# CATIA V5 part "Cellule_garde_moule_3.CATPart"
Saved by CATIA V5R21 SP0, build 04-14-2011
Part number: Moule_cellule_garde.1
Bounding box of the stored display mesh (mm): x -18 to 18, y -75 to 75, z -17 to 0
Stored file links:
  C:\Users\zerma\Pictures\Moule_3\Cellule_garde_moule_3.CATPart
  Product1.CATProduct
  C:\Users\zerma\Pictures\Moule\Moule_v1.CATPart
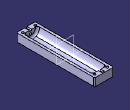
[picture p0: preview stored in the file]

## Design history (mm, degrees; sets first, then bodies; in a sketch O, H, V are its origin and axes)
Body1 (main body)
  Sketch1 on yz-plane, origin (0, 0, 0), H (0, 1, 0), V (0, 0, 1)
    line L1 (-95, -12.5) -> (95, -12.5)
    point P1 (-95, -12.5)
    line L2 (-100, -15) -> (100, -15)
    point P3 (-100, -15)
    line L3 (-95, -12.5) -> (-95, 0)
    point P5 (-95, 0)
    line L4 (-100, -15) -> (-100, 0)
    point P6 (-100, 0)
    line L5 (-95, 0) -> (-100, 0)
    point P7 (100, 0)
    point P8 (100, -15)
    line L6 (100, -15) -> (100, 0)
    point P9 (95, 0)
    line L7 (95, 0) -> (100, 0)
    point P10 (95, -12.5)
    line L8 (95, -12.5) -> (95, 0)
    distance L1 H = 12.5
    distance L1 L2 = 2.5
    length L4 = 15
    distance L4 L3 = 5
    length L1 = 190
    length L2 = 200
    distance V L3 = 95
    horizontal: L1 H, L2 H, L5 H
    vertical: L3 V, L4 V
    symmetry: P6 P7 V, P3 P8 V, L4 L6 V, P5 P9 V, L5 L7 V, P1 P10 V, L3 L8 V
  Shaft1: profile Sketch1, axis Sketch1.H, angle 360
  Sketch2 on face of Shaft1 from Sketch1.L4, origin (0, -100, 0), H (1, 0, 0), V (0, 0, 1)
    line L1 (-10, 2.5) -> (10, 2.5)
    line L2 (10, 2.5) -> (10, -2.5)
    line L3 (10, -2.5) -> (-10, -2.5)
    line L4 (-10, -2.5) -> (-10, 2.5)
    length L2 = 5
    length L1 = 20
    horizontal: L1 H, L3 H
    vertical: L2 V, L4 V
    symmetry: L3 L1 H, L4 L2 V
  Pad1: profile Sketch2, direction (0, -1, 0), length 15
  Sketch3 on face of Pad1 from Sketch2.L1, origin (0, 0, 2.5), H (1, 0, 0), V (0, 1, 0)
    circle A1 centre (0, -107.5) radius 2.5
    point P1 (0, -107.5)
    reference intersected line E1 (14.7902, -100) -> (-14.7902, -100) from face of Shaft1 from Sketch1.L4
    radius A1 = 2.5
    distance P1 E1 = 7.5
    coincidence: P1 V
  Pocket1: profile Sketch3, direction (0, 0, -1), length 5, mirrored extent
  Fillet1: radius 2, on edge [face of Pad1 from Sketch2.L4 | end face of Pad1]; edge [face of Pad1 from Sketch2.L1 | end face of Pad1]; edge [face of Pad1 from Sketch2.L3 | end face of Pad1]; edge [face of Pad1 from Sketch2.L2 | end face of Pad1]; edge [face of Pad1 from Sketch2.L2 | face of Pad1 from Sketch2.L3]; edge [face of Shaft1 from Sketch1.L4 | face of Pad1 from Sketch2.L3]; edge [face of Pad1 from Sketch2.L3 | face of Pad1 from Sketch2.L4]; edge [face of Pocket1 from Sketch3.A1 | face of Pad1 from Sketch2.L3]; edge [face of Pad1 from Sketch2.L4 | face of Pad1 from Sketch2.L1]; edge [face of Pad1 from Sketch2.L1 | face of Pad1 from Sketch2.L2]; edge [face of Shaft1 from Sketch1.L4 | face of Pad1 from Sketch2.L1]; edge [face of Shaft1 from Sketch1.L4 | face of Pad1 from Sketch2.L4]; edge [face of Shaft1 from Sketch1.L4 | face of Pad1 from Sketch2.L2]; face of Pad1 from Sketch2.L1
  Mirror1: of Pad1, Pocket1, Fillet1, about zx-plane
  Fillet2: radius 4, on edge [face of Shaft1 from Sketch1.L2 | face of Shaft1 from Sketch1.L6]; edge [face of Shaft1 from Sketch1.L4 | face of Shaft1 from Sketch1.L2]
Body2
  Sketch4 on xy-plane, origin (0, 0, 0), H (1, 0, 0), V (0, 1, 0)
    line L1 (18, 75) -> (18, -75)
    line L2 (18, -75) -> (-18, -75)
    line L3 (-18, -75) -> (-18, 75)
    line L4 (-18, 75) -> (18, 75)
    length L4 = 36
    length L1 = 150
    vertical: L1 V, L3 V
    horizontal: L2 H, L4 H
    equidistance: L1 L3 O, L2 L4 O
  Pad2: profile Sketch4, direction (0, 0, -1), length 17
  Body3
    Sketch5 on yz-plane, origin (0, 0, 0), H (0, 1, 0), V (0, 0, 1)
      line L1 (-61, -5.5) -> (61, -5.5)
      point P1 (-61, -5.5)
      point P2 (61, -5.5)
      line L2 (-66, -13.5) -> (66, -13.5)
      point P3 (-66, -13.5)
      point P4 (66, -13.5)
      line L3 (-61, -5.5) -> (-61, 0)
      point P5 (-61, 0)
      line L4 (-66, -13.5) -> (-66, -2.5)
      point P6 (-66, -2.5)
      point P7 (66, -2.5)
      point P8 (66, -13.5)
      line L5 (66, -13.5) -> (66, -2.5)
      point P9 (61, 0)
      point P10 (61, -5.5)
      line L6 (61, -5.5) -> (61, 0)
      line L7 (-66, -2.5) -> (-78, -2.5)
      line L8 (-78, -2.5) -> (-78, 0)
      line L9 (-78, 0) -> (-61, 0)
      point P13 (-61, 0)
      line L10 (66, -2.5) -> (73, -2.5)
      line L11 (73, -2.5) -> (73, 0)
      line L12 (73, 0) -> (61, 0)
      distance L1 H = 5.5
      distance L1 L2 = 8
      distance L4 L3 = 5
      distance V L3 = 61
      length L9 = 17
      length L12 = 12
      length L11 = 2.5
      horizontal: L1 H, L2 H, L7 H, L9 H, L10 H, L12 H
      vertical: L3 V, L4 V, L8 V, L11 V
      symmetry: P6 P7 V, P3 P8 V, L4 L5 V, P5 P9 V, P1 P10 V, L3 L6 V
      coincidence: P13 P5, L9 H, P4 P8, P2 P10
    Shaft2: profile Sketch5, axis Sketch5.H, angle 360
  Remove1: tool Body3
  Sketch6 on face of Shaft2 from Sketch5.L6, origin (0, 61, 0), H (-1, 0, 0), V (0, 0, 1)
    circle A1 centre (0, 0) radius 5.5
    reference projected circle E1 centre (0, 0) radius 5.5 from edge [face of Shaft2 from Sketch5.L1 | face of Shaft2 from Sketch5.L6]
    reference projected circle E2 centre (0, 0) radius 5.5 from edge [face of Shaft2 from Sketch5.L1 | face of Shaft2 from Sketch5.L6]
    coincidence: A1 E1
    concentricity: A1 E2
  Pocket2: profile Sketch6, direction (0, -1, 0), up to face of Shaft2 from Sketch5.L3
  Sketch7 on end face of Pad2, origin (0, 0, -17), H (1, 0, 0), V (0, -1, 0)
    circle A1 centre (12, 69) radius 2.25
    point P1 (12, 69)
    circle A2 centre (12, -69) radius 2.25
    circle A3 centre (-12, 69) radius 2.25
    circle A4 centre (-12, -69) radius 2.25
    reference projected line E1 (18, 75) -> (18, -75) from edge [end face of Pad2 | face of Pad2 from Sketch4.L1]
    reference projected line E2 (-18, 75) -> (18, 75) from edge [end face of Pad2 | face of Pad2 from Sketch4.L2]
    radius A1 = 2.25
    distance P1 E1 = 6
    distance P1 E2 = 6
    symmetry: A1 A2 H, A1 A3 V, A3 A4 H
  Pocket3: profile Sketch7, direction (0, 0, 1), length 50, mirrored extent
  Chamfer1: length 2, angle 45, on edge [end face of Pad2 | face of Pad2 from Sketch4.L2]; edge [end face of Pad2 | face of Pad2 from Sketch4.L3]; edge [end face of Pad2 | face of Pad2 from Sketch4.L4]; edge [end face of Pad2 | face of Pad2 from Sketch4.L1]; edge [face of Pad2 from Sketch4.L1 | face of Pad2 from Sketch4.L4]; edge [face of Pad2 from Sketch4.L4 | face of Pad2 from Sketch4.L3]; edge [face of Pad2 from Sketch4.L2 | face of Pad2 from Sketch4.L1]; edge [face of Pad2 from Sketch4.L3 | face of Pad2 from Sketch4.L2]
  Sketch8 on end face of Pad2, origin (0, 0, -17), H (1, 0, 0), V (0, -1, 0)
    circle A1 centre (12, 69) radius 3.5
    reference projected circle E1 centre (12, 69) radius 2.25 from edge [face of Pocket3 from Sketch7.A1 | end face of Pad2]
    circle A2 centre (12, -69) radius 3.5
    circle A3 centre (-12, 69) radius 3.5
    circle A4 centre (-12, -69) radius 3.5
    radius A1 = 3.5
    concentricity: A1 E1
    symmetry: A1 A2 H, A1 A3 V, A3 A4 H
  Pocket4: profile Sketch8, direction (0, 0, 1), length 8
  Fillet3: radius 4, on edge [face of Shaft2 from Sketch5.L5 | face of Shaft2 from Sketch5.L2]
  Fillet4: radius 4, on edge [face of Shaft2 from Sketch5.L2 | face of Shaft2 from Sketch5.L4]
  DatumCurve1
  Sketch9 on start face of Pad2, origin (0, 0, 0), H (1, 0, 0), V (0, 1, 0)
    circle A1 centre (0, 56) radius 1
    point P1 (0, 56)
    reference projected line E1 (28, 118) -> (28, -118) from edge of DatumCurve1
    reference projected line E2 (18, 75) -> (-18, 75) from edge [face of Pad2 from Sketch4.L4 | start face of Pad2]
    circle A2 centre (0, -56) radius 1
    radius A1 = 1
    distance P1 E1 = 28
    distance P1 E2 = 19
    symmetry: A1 A2 H
  Pocket5: profile Sketch9, direction (0, 0, -1), through (limit type 6)
  Sketch10 on face of Shaft2 from Sketch5.L4, origin (0, -66, 0), H (-1, 0, 0), V (0, 0, 1)
    circle A1 centre (0, -6.5) radius 2
    point P1 (0, -6.5)
    reference projected line E1 (13.5, 0) -> (2.5, 0) from edge [start face of Pad2 | face of Shaft2 from Sketch5.L4]
    radius A1 = 2
    distance P1 E1 = 6.5
  Pocket6: profile Sketch10, direction (0, -1, 0), length 13, mirrored extent
  CLDGeom1 "Maillage.1"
